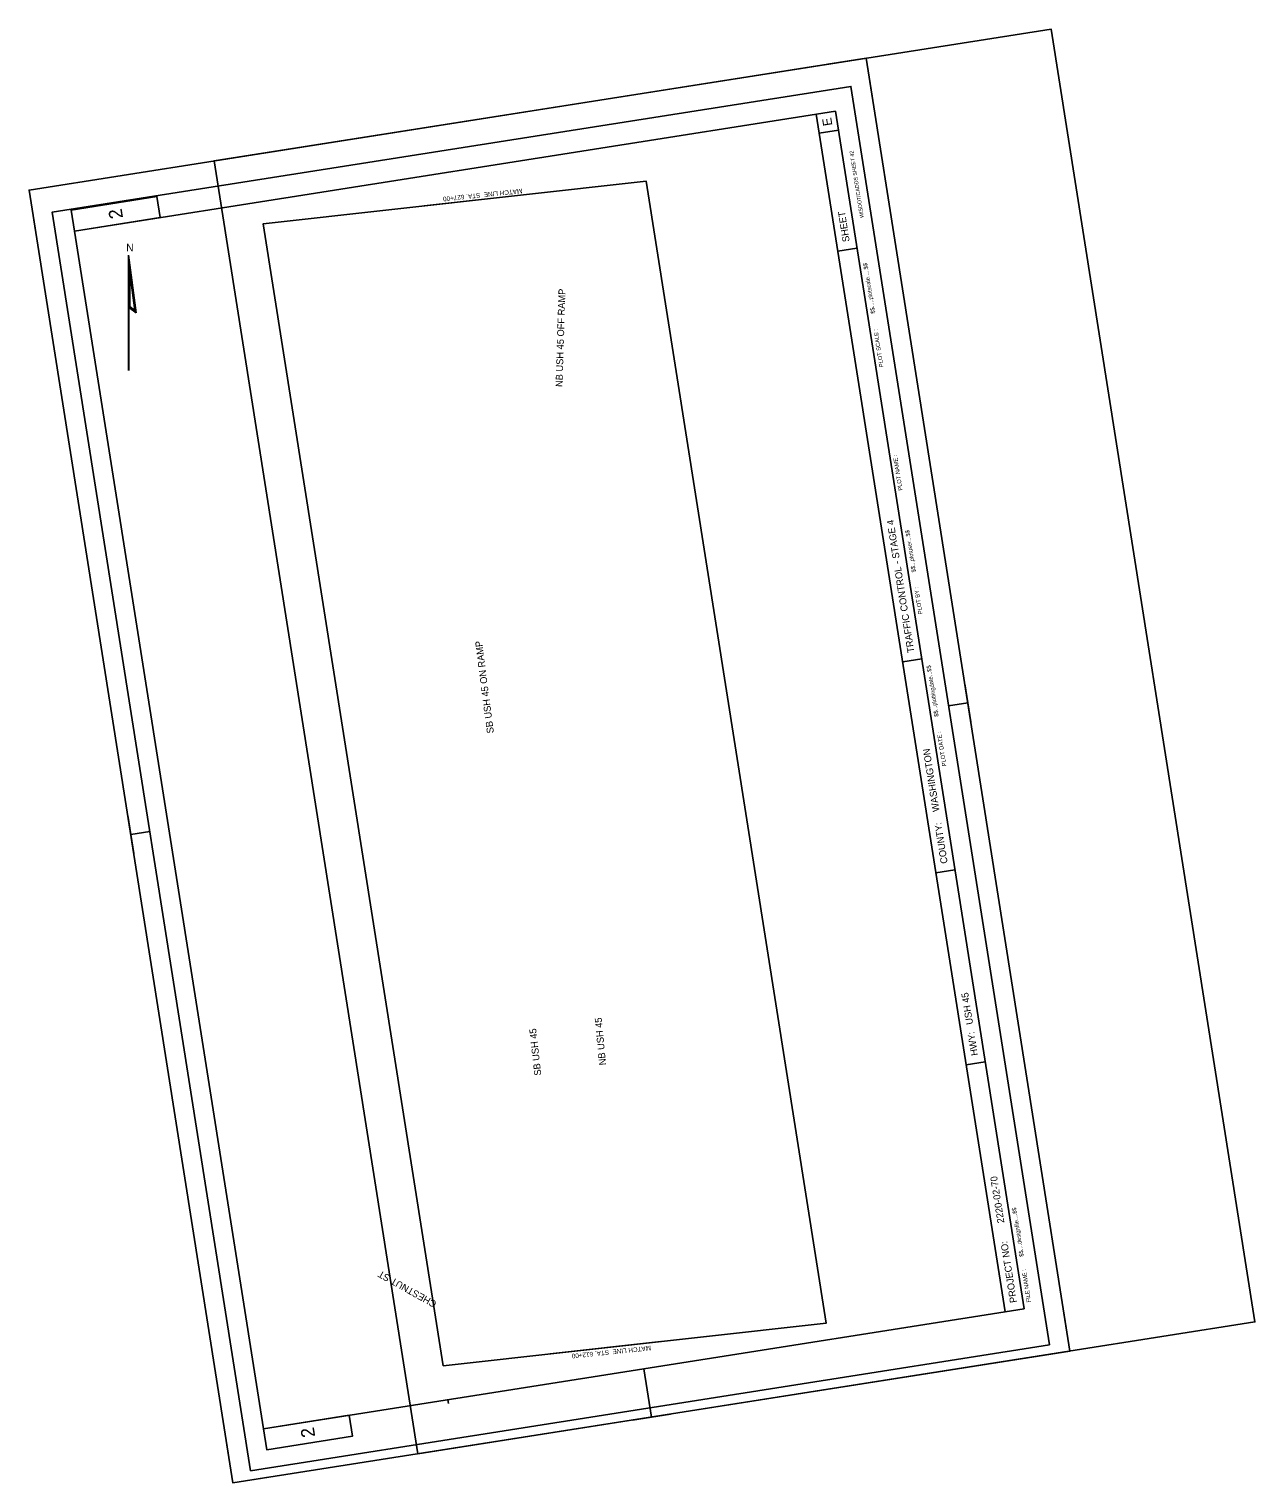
# Model space of a CAD drawing. Extents: x 355099 to 356691, y 183238 to 185127.
import ezdxf

# ---------------------------------------------------------------- set-up
doc = ezdxf.new("R2010")
doc.units = 0
for name, color, linetype in [('Default', 7, 'Continuous'), ('P_ALI_100_PIData', 7, 'Continuous'), ('P_ALI_20', 7, 'Continuous'), ('P_ALI_50_Equation', 7, 'Continuous'), ('P_ALI_50_PIData', 7, 'Continuous'), ('P_ALI_50_Sta', 7, 'Continuous'), ('P_ALI_50_Tic', 7, 'Continuous')]:
    doc.layers.add(name, color=color, linetype=linetype)

msp = doc.modelspace()

# ---------------------------------------------------------------- linework, layer by layer
msp.add_lwpolyline([(355604, 183276.2), (355339.3, 184955.5), (356425.9, 185126.8), (356690.6, 183447.5), (355604, 183276.2)])
at = {"layer": 'Default'}
msp.add_lwpolyline([(355636.6, 183390.5), (356134.1, 183446), (355900.3, 184929.2), (355402.9, 184873.7)], close=True, dxfattribs=at)
msp.add_lwpolyline([(355636.6, 183390.5), (356134.1, 183446), (355900.3, 184929.2), (355402.9, 184873.7)], close=True, dxfattribs=at)
at = {"layer": 'P_ALI_100_PIData'}
for p, q in [((355238.3, 184758.1), (355228.3, 184833.1)), ((355228.3, 184765.6), (355228.3, 184833.1)), ((355229.1, 184765.9), (355229.1, 184821.8)), ((355237.3, 184759.7), (355229.1, 184821.8)), ((355229.8, 184766.3), (355229.8, 184810.5)), ((355236.4, 184761.4), (355229.8, 184810.5)), ((355228.3, 184765.6), (355238.3, 184758.1)), ((355228.3, 184683.1), (355228.3, 184765.6)), ((355228.6, 184683.1), (355228.6, 184765.4)), ((355229.1, 184765.9), (355237.3, 184759.7)), ((355229.8, 184766.3), (355236.4, 184761.4))]:
    msp.add_line(p, q, dxfattribs=at)
msp.add_lwpolyline([(355228.3, 184833), (355228.3, 184833)], dxfattribs=at)
at = {"layer": 'P_ALI_20'}
for p, q in [((356185.7, 185088.9), (356136.3, 185081.1)), ((356193.5, 185039.5), (356185.7, 185088.9)), ((356145.9, 185020.1), (355158.1, 184864.4)), ((356366.5, 183460.4), (356121.2, 185016.2)), ((356391.2, 183464.3), (356145.9, 185020.1)), ((356149.8, 184995.4), (356125.1, 184991.5)), ((355148.5, 184925.4), (355099.1, 184917.6)), ((355106.9, 184868.3), (355099.1, 184917.6)), ((355403.4, 183308.6), (355158.1, 184864.4)), ((356174, 184842.3), (356149.3, 184838.4)), ((356258, 184308.9), (356233.3, 184305)), ((356321.6, 184227), (356313.8, 184276.4)), ((356317.7, 184251.7), (356293, 184247.8)), ((355235, 184055.8), (355227.2, 184105.2)), ((355231.1, 184080.5), (355255.8, 184084.4)), ((356301.2, 184034.8), (356276.5, 184030.9)), ((356340.6, 183785.4), (356315.9, 183781.5)), ((356391.2, 183464.3), (355403.4, 183308.6)), ((356450.4, 183409.6), (356442.6, 183459)), ((355891.4, 183423.5), (355891.4, 183423.5)), ((356450.4, 183409.6), (356401, 183401.9)), ((355907.1, 183324), (355897.3, 183386.5)), ((355642.9, 183346.4), (355643.7, 183341.5)), ((355931.8, 183327.9), (355882.4, 183320.1)), ((355363.8, 183238.4), (355356, 183287.8)), ((355413.2, 183246.2), (355363.8, 183238.4))]:
    msp.add_line(p, q, dxfattribs=at)
for points in [[(355158.1, 184864.4), (355153.9, 184891.6), (355265, 184909.1), (355269.3, 184881.9)], [(355403.4, 183308.6), (355407.6, 183281.5), (355518.8, 183299), (355514.5, 183326.2)]]:
    msp.add_lwpolyline(points, close=True, dxfattribs=at)
at = {"layer": 'P_ALI_50_Equation'}
msp.add_lwpolyline([(355363.8, 183238.4), (355099.1, 184917.6), (356185.7, 185088.9), (356450.4, 183409.6)], close=True, dxfattribs=at)
at = {"layer": 'P_ALI_50_PIData'}
for p, q in [((355612.2, 184897.1), (355748.9, 184912.3)), ((355775.6, 183406), (355919.5, 183422))]:
    msp.add_line(p, q, dxfattribs=at)
at = {"layer": 'P_ALI_50_Tic'}
for points in [[(356450.4, 183409.6), (356185.7, 185088.9), (355099.1, 184917.6), (355363.8, 183238.4)], [(356423.8, 183417.6), (356166.2, 185052.4), (355129, 184888.9), (355386.6, 183254.1)]]:
    msp.add_lwpolyline(points, close=True, dxfattribs=at)

# ---------------------------------------------------------------- texts
at = {"layer": 'P_ALI_100_PIData'}
msp.add_text('N', height=10, dxfattribs=at).set_placement((355225.2, 184838))
at = {"layer": 'P_ALI_20'}
for s, height, p in [('E', 12, (356142.1, 185001.9)), ('WISDOT/CADDS SHEET 42', 5, (356182.9, 184881.9)), ('2', 17.5, (355221.2, 184881.7)), ('SHEET ', 9, (356164.5, 184851)), ('$$.....plotscale.....$$', 5.4, (356197.5, 184757.4)), ('PLOT SCALE : ', 5.4, (356208.4, 184688.1)), ('PLOT NAME :                      ', 5.4, (356233.2, 184527.7)), ('TRAFFIC CONTROL - STAGE 4', 9, (356248.6, 184317.5)), ('$$...plotuser...$$', 5.4, (356250.4, 184421.6)), ('PLOT BY :', 5.4, (356259, 184367.3)), ('$$...plottingdate...$$', 5.4, (356280, 184233.9)), ('PLOT DATE :', 5.4, (356290.1, 184169.7)), (' WASHINGTON', 9, (356281.7, 184107.6)), ('COUNTY:', 9, (356291.8, 184043.4)), (' USH 45', 9, (356325.3, 183831)), ('HWY:', 9, (356331.1, 183794)), (' 2220-02-70', 9, (356365.9, 183573.2)), ('$$....designfile....$$', 5.4, (356390.5, 183532.6)), ('PROJECT NO:', 9, (356381.7, 183473)), ('FILE NAME :', 5.4, (356399.9, 183473.3)), ('2', 17.5, (355470.7, 183298.7))]:
    msp.add_text(s, height=height, rotation=98.957, dxfattribs=at).set_placement(p)
at = {"layer": 'P_ALI_50_Sta'}
for s, height, rotation, p in [('MATCH LINE  STA. 627+00', 6, 185.9528, (355739.1, 184919.6)), ('NB USH 45 OFF RAMP', 9, 88.2394, (355791.6, 184661.8)), ('SB USH 45 ON RAMP', 9, 97.3611, (355702.6, 184212.6)), ('NB USH 45', 9, 95.406, (355848.3, 183781.3)), ('SB USH 45', 9, 96.3654, (355764.2, 183767.9)), ('CHESTNUT ST', 9, 150.8316, (355629, 183473.5)), ('MATCH LINE  STA. 612+00', 6, 185.9528, (355906.2, 183416.7))]:
    msp.add_text(s, height=height, rotation=rotation, dxfattribs=at).set_placement(p)

doc.saveas('drawing.dxf')
